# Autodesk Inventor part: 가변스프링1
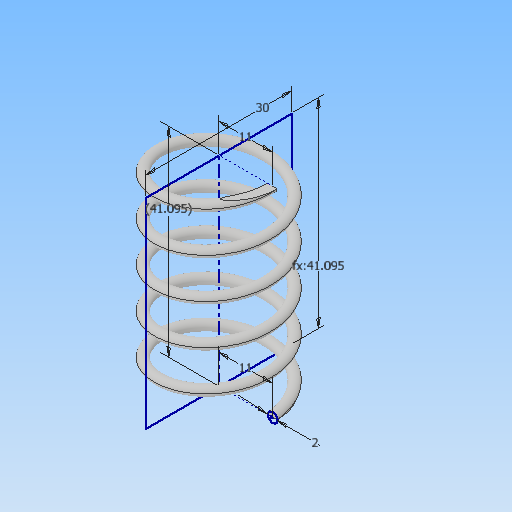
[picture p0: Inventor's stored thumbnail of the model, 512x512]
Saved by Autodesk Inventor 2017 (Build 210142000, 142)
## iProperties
Part Number: 가변스프링1
Material: 일반
Document SubType Name: Modeling
Designer: MRC
Density: 1 g/cm^3
Appearance: 기본값
Mass: 1.07473 g
Surface Area: 21.7438 cm^2
Volume: 1.07473 cm^3
Author: MRC
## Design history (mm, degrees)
sketch "스케치1"
  geometry: L1 (0, 0)-(0, 41.095); L2 (0, 41.095)-(11, 41.095); L3 (0, 0)-(11, 0); C1 r 1 at (11, 0)
  constraints: 6 end point, 2 horizontal, 1 centre point, 1 coincident, 1 vertical
  dimensions: "d0" = 41.0955 distance of L1.start L1.end (derived); "d1" = 11 distance of L1.end L2.end; "d2" = 11 distance of L1.start L3.end; "d3" = 2 diameter of C1
feature "코일1" sketch "스케치1" pitch "d4" = 10; turns "d6" = 5; dims "d5" = 41.0955 (= d0), "d7" = 0, angle "d8" = 90 deg, angle "d9" = 90 deg, "d10" = 0, "d11" = 0
sketch "스케치2"
  geometry: L1 (41.095, 15)-(0, 15); L2 (0, 15)-(0, -15); L3 (0, -15)-(41.095, -15); L4 (41.095, -15)-(41.095, 15); 2 further points
  constraints: 8 end point, 2 parallel, 1 coincident, 1 horizontal, 1 midpoint, 1 perpendicular
  dimensions: "d12" = 41.0955 distance of L2.end L3.end (= d0); "d13" = 30 distance of L3.end L1.start
extrude "돌출1" sketch "스케치2" stored distance "d14" = 0; taper "d15" = 0 deg
node "솔리드1"
